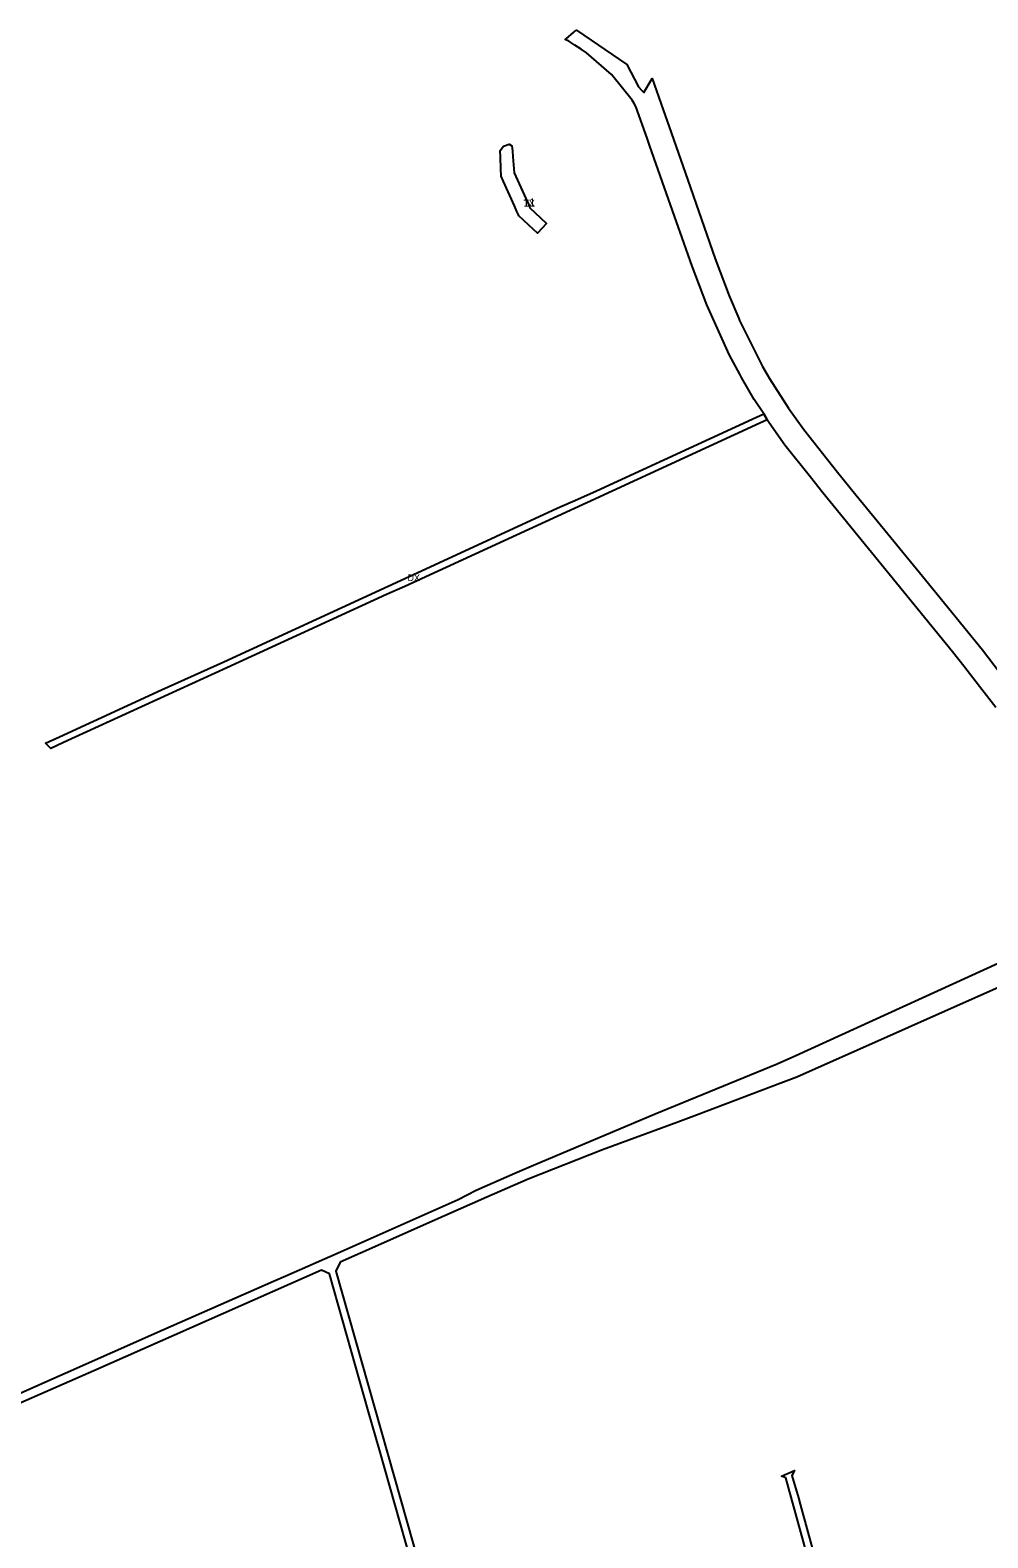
# Model space of a CAD drawing. Extents: x -521882 to -518995, y -1142400 to -1140153.
# Drawn here: x -521453 to -520739, y -1141277 to -1140153 of the extents above; entities that cross this region are included whole.
import ezdxf

# ---------------------------------------------------------------- set-up
doc = ezdxf.new("R2010")
doc.units = 0
for name, color, linetype in [('90320013', 7, 'Continuous'), ('90370013', 7, 'Continuous'), ('90440023', 7, 'Continuous'), ('ID_navrh', 7, 'Continuous')]:
    doc.layers.add(name, color=color, linetype=linetype)

msp = doc.modelspace()

# ---------------------------------------------------------------- linework, layer by layer
at = {"layer": '90320013'}
msp.add_lwpolyline([(-520733.42, -1140657.97), (-520745.42, -1140642.26), (-520757.18, -1140627.06), (-520765.71, -1140616.57), (-520862.22, -1140497.87), (-520871.65, -1140486.28), (-520890.58, -1140462.46), (-520902.4, -1140445.74), (-520903.84, -1140443.54), (-520906.37, -1140439.12), (-520913.58, -1140428.33), (-520923.06, -1140411.9), (-520924.28, -1140409.64), (-520930.52, -1140398.04), (-520931.92, -1140395.43), (-520948.85, -1140357.77), (-520959.74, -1140329.07), (-520978.89, -1140274.79), (-520991.34, -1140239.5), (-520993.36, -1140233.77), (-521001.72, -1140210.08), (-521002.93, -1140207.73), (-521004.56, -1140205.45), (-521019.82, -1140186.27), (-521038.45, -1140170.03), (-521042.52, -1140167.42), (-521047.19, -1140164.44), (-521051.86, -1140161.45), (-521054.36, -1140160.13), (-521053.72, -1140159.58), (-521048.05, -1140154.68), (-521047.4, -1140154.12), (-521045.99, -1140153.16), (-521008.55, -1140178.79), (-520999.73, -1140195.29), (-520997.26, -1140198.03), (-520995.82, -1140199.62), (-520989.57, -1140189.1), (-520981.4, -1140212.45), (-520975.5, -1140229.32), (-520963.03, -1140264.99), (-520942.5, -1140323.7), (-520932.27, -1140351.12), (-520925.04, -1140368.05), (-520924.44, -1140369.44), (-520915.77, -1140387.04), (-520907.24, -1140403.74), (-520902.19, -1140412.67), (-520887.82, -1140434.78), (-520876.46, -1140450.75), (-520851.49, -1140482.48), (-520837.71, -1140499.35), (-520813.81, -1140528.62), (-520785.9, -1140562.81), (-520743.28, -1140615.01), (-520730.64, -1140631.58)], dxfattribs=at)
at = {"layer": '90370013'}
msp.add_lwpolyline([(-520909.31, -1140446.06), (-521038.29, -1140505.39), (-521174.07, -1140567.72), (-521187.8, -1140573.75), (-521306.81, -1140628.37), (-521428.47, -1140683.93), (-521438.02, -1140688.47), (-521441.99, -1140684.63), (-521431.42, -1140679.77), (-521355.48, -1140644.9), (-521309.07, -1140623.96), (-521152, -1140551.52), (-521060.49, -1140509.3), (-521045.09, -1140502.65), (-521031.07, -1140496.4), (-520911.89, -1140441.66), (-520906.37, -1140439.12), (-520903.84, -1140443.54)], close=True, dxfattribs=at)
for points in [[(-521692.02, -1141284.07), (-521705, -1141272.16), (-521696.71, -1141273.51), (-521531.28, -1141200.09), (-521478.81, -1141176.87), (-521464.85, -1141170.68), (-521354.37, -1141121.84), (-521271.86, -1141085.49), (-521262.72, -1141081.47), (-521223.67, -1141064.26), (-521134.18, -1141024.63), (-521120.79, -1141017.67), (-521091.97, -1141005.03), (-521077.97, -1140999.02), (-520987.34, -1140960.66), (-520896.33, -1140923.45), (-520882.47, -1140917.37), (-520708.35, -1140837.86)], [(-520715.12, -1140859.45), (-520881.74, -1140933.43), (-520893.74, -1140937.98), (-520956.56, -1140961.79), (-520970.5, -1140967.09), (-521026.59, -1140987.63), (-521082.18, -1141009.47), (-521112.83, -1141022.98), (-521155.63, -1141041.85), (-521191.96, -1141057.88), (-521222.3, -1141071.25), (-521225.53, -1141078.04), (-521177.35, -1141247.92), (-521153.24, -1141332.9)], [(-521157.91, -1141334.94), (-521192.96, -1141211.21), (-521201.01, -1141182.77), (-521230.09, -1141080.11), (-521236.08, -1141077.32), (-521405.94, -1141152.24), (-521460.33, -1141176.23), (-521474.13, -1141182.35), (-521609.81, -1141242.59), (-521691.15, -1141278.7)], [(-520851.22, -1141372.34), (-520889.86, -1141232.13), (-520893.13, -1141230.74), (-520883.56, -1141226.59), (-520885.33, -1141230.38), (-520880.53, -1141246.97), (-520879.25, -1141251.61), (-520841.7, -1141388.53)]]:
    msp.add_lwpolyline(points, dxfattribs=at)
at = {"layer": '90440023'}
msp.add_lwpolyline([(-521092.32, -1140284.11), (-521100.5, -1140265.83), (-521102.24, -1140261.94), (-521102.44, -1140256.49), (-521102.76, -1140247.73), (-521102.93, -1140242.86), (-521100.42, -1140239.62), (-521096.26, -1140238.22), (-521094.12, -1140239.48), (-521093.8, -1140243.17), (-521093.43, -1140247.58), (-521092.42, -1140259.41), (-521083.79, -1140278.7), (-521081.89, -1140282.94), (-521081.11, -1140284.7), (-521080.73, -1140285.54), (-521072.76, -1140293.07), (-521068.35, -1140297.23), (-521075.22, -1140304.5), (-521081.54, -1140298.53), (-521089.05, -1140291.44), (-521089.34, -1140290.78), (-521090.43, -1140288.34)], close=True, dxfattribs=at)

# ---------------------------------------------------------------- texts
at = {"layer": '90370013'}
msp.add_text('DX', height=5, rotation=0, dxfattribs=at).set_placement((-521172.07, -1140563.8))
at = {"layer": '90440023'}
msp.add_text('TX', height=5, rotation=360, dxfattribs=at).set_placement((-521085.64, -1140284.61))
at = {"layer": 'ID_navrh'}
msp.add_text('11', height=6, rotation=0, dxfattribs=at).set_placement((-521085.64, -1140284.61))

doc.saveas('drawing.dxf')
